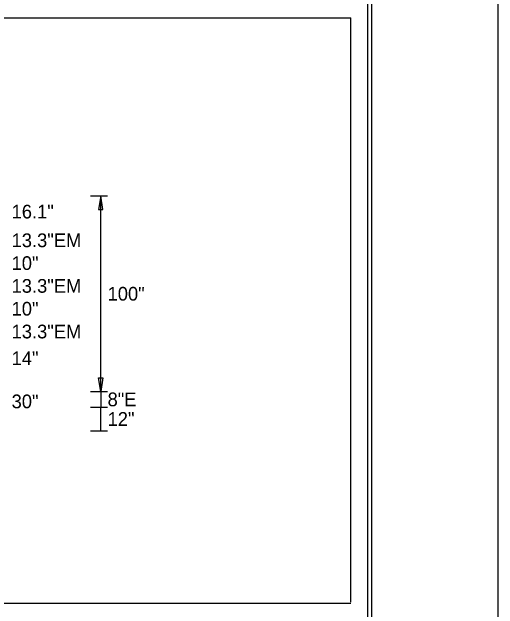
# Model space of a CAD drawing. Extents: x 17890071 to 17890754, y 17897628 to 17897992.
# Drawn here: x 17890211.96 to 17890232.65, y 17897794.03 to 17897819.45 of the extents above; entities that cross this region are included whole.
import ezdxf

# ---------------------------------------------------------------- set-up
doc = ezdxf.new("R2010")
doc.units = 0
for name, color, linetype in [('GSDims', 7, 'Continuous'), ('PlotBorder_dp', 7, 'Continuous'), ('SheetBorder_dp', 7, 'Continuous'), ('SheetLinesMisc1_dp', 7, 'Continuous'), ('SheetLinesMisc2_dp', 7, 'Continuous')]:
    doc.layers.add(name, color=color, linetype=linetype)

msp = doc.modelspace()

# ---------------------------------------------------------------- linework, layer by layer
at = {"layer": 'GSDims'}
for p, q in [((17890215.302, 17897811.621), (17890216.032, 17897811.621)), ((17890215.74, 17897803.288), (17890215.74, 17897811.621)), ((17890215.302, 17897803.288), (17890216.032, 17897803.288)), ((17890215.302, 17897803.288), (17890216.032, 17897803.288)), ((17890215.74, 17897803.288), (17890215.74, 17897802.621)), ((17890215.302, 17897802.621), (17890216.032, 17897802.621)), ((17890215.302, 17897802.621), (17890216.032, 17897802.621)), ((17890215.74, 17897801.621), (17890215.74, 17897802.621)), ((17890215.302, 17897801.621), (17890216.032, 17897801.621))]:
    msp.add_line(p, q, dxfattribs=at)
for points in [[(17890215.74, 17897811.621), (17890215.643, 17897811.038), (17890215.837, 17897811.038)], [(17890215.74, 17897803.288), (17890215.643, 17897803.871), (17890215.837, 17897803.871)]]:
    msp.add_lwpolyline(points, close=True, dxfattribs=at)
at = {"layer": 'PlotBorder_dp'}
msp.add_lwpolyline([(17890071.13, 17897766.734), (17890232.646, 17897766.734), (17890232.646, 17897870.495), (17890071.13, 17897870.495)], close=True, dxfattribs=at)
at = {"layer": 'SheetBorder_dp'}
msp.add_line((17890227.262, 17897869.516), (17890227.262, 17897767.712), dxfattribs=at)
at = {"layer": 'SheetLinesMisc1_dp'}
msp.add_line((17890152.385, 17897819.209), (17890226.387, 17897819.209), dxfattribs=at)
at = {"layer": 'SheetLinesMisc2_dp'}
for p, q in [((17890227.099, 17897775.777), (17890227.099, 17897869.435)), ((17890152.385, 17897819.209), (17890226.387, 17897819.209)), ((17890175.209, 17897819.209), (17890226.38, 17897819.209)), ((17890226.38, 17897794.319), (17890226.38, 17897819.209)), ((17890226.379, 17897797.146), (17890226.379, 17897797.179)), ((17890175.209, 17897794.284), (17890226.38, 17897794.284))]:
    msp.add_line(p, q, dxfattribs=at)

# ---------------------------------------------------------------- texts
at = {"layer": 'GSDims'}
for s, p in [('16.1"', (17890211.948, 17897810.66)), ('13.3"EM', (17890211.948, 17897809.438)), ('10"', (17890211.948, 17897808.467)), ('13.3"EM', (17890211.948, 17897807.496)), ('100"', (17890216.032, 17897807.163)), ('10"', (17890211.948, 17897806.525)), ('13.3"EM', (17890211.948, 17897805.554)), ('14"', (17890211.948, 17897804.415)), ('8"E', (17890216.032, 17897802.663)), ('30"', (17890211.948, 17897802.579)), ('12"', (17890216.032, 17897801.829))]:
    msp.add_text(s, height=0.5833, dxfattribs=at).set_placement(p)

doc.saveas('drawing.dxf')
